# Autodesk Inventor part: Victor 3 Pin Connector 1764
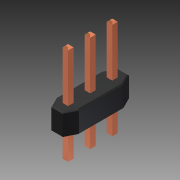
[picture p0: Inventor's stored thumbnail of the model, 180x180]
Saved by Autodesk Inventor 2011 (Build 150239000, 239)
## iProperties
Shininess: 64.0
Length Units: 11272
Angle Units: 11279
Time Units: 11290
Mass Units: 11286
Length Display Precision: 3
Angle Display Precision: 2
Compacted: True
Part Number: Victor 3 Pin Connector 1764
Document SubType Name: Modeling
Created: 2005-12
Designer: Owner
Material: ABS Plastic
Density: 1 g/cm^3
Density: 0.0
Volumn: 0.0
Area: 0.0
PropertySet Name: Model Information
Control State: 0
Master: False
Checked Out: False
Author: Owner
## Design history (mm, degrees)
sketch "Sketch1"
  geometry: L1 (0, 0)-(2.54, 0); L2 (2.54, 0)-(2.54, 7.62); L3 (2.54, 7.62)-(0, 7.62); L4 (0, 7.62)-(0, 0); L5 (0.953, 4.128)-(1.587, 4.128); L6 (1.587, 4.128)-(1.587, 3.493); L7 (1.587, 3.493)-(0.953, 3.493); L8 (0.953, 3.493)-(0.953, 4.128); L9 (0.953, 1.587)-(1.587, 1.587); L10 (1.587, 1.587)-(1.587, 0.953); L11 (1.587, 0.953)-(0.953, 0.953); L12 (0.953, 0.953)-(0.953, 1.587); L13 (0.953, 3.81)-(0, 3.81); L14 (1.587, 1.27)-(2.54, 1.27); L15 (0.953, 6.033)-(1.587, 6.033); L16 (1.587, 6.033)-(1.587, 6.667); L17 (1.587, 6.667)-(0.953, 6.667); L18 (0.953, 6.667)-(0.953, 6.033)
  constraints: 36 end point, 8 parallel, 6 equal length, 6 perpendicular, 4 horizontal, 3 midpoint, 2 collinear, 1 point on line, 1 other
  dimensions: "d3" = 2.54 distance of L1.start L1.end; "d4" = 7.62 distance of L3.end L1.start; "d5" = 0.635 distance of L5.end L6.end; "d6" = 2.54 distance between parallel lines of L11 L7; "d7" = 0.9525 distance between parallel lines of L1 L11; "d25" = 2.54 distance between parallel lines of L17 L5
extrude "Extrusion1" new body sketch "Sketch1" distance "d8" = 2.54; taper "d9" = 0 deg
chamfer "Chamfer1" distance "d10" = 1.27; stored, may be unused: second distance "d11" = 0.635, angle "d26" = 45 deg
chamfer "Chamfer2" distance "d12" = 1.27; stored, may be unused: second distance "d13" = 0.635, angle "d27" = 45 deg
chamfer "Chamfer3" distance "d14" = 1.27; stored, may be unused: second distance "d15" = 0.635, angle "d28" = 45 deg
chamfer "Chamfer4" distance "d16" = 1.27; stored, may be unused: second distance "d17" = 0.635, angle "d29" = 45 deg
workplane "Work Plane1"
sketch "Sketch2"
  geometry: L1 (-1.587, 4.128)-(-0.953, 4.128) reference; L2 (-1.587, 3.493)-(-1.587, 4.128) reference; L3 (-0.953, 4.128)-(-0.953, 3.493) reference; L4 (-0.953, 3.493)-(-1.587, 3.493) reference; L5 (-1.587, 1.587)-(-0.953, 1.587) reference; L6 (-0.953, 1.587)-(-0.953, 0.953) reference; L7 (-0.953, 0.953)-(-1.587, 0.953) reference; L8 (-1.587, 0.953)-(-1.587, 1.587) reference; L9 (-0.953, 6.667)-(-0.953, 6.033) reference; L10 (-0.953, 6.033)-(-1.587, 6.033) reference; L11 (-1.587, 6.033)-(-1.587, 6.667) reference; L12 (-1.587, 6.667)-(-0.953, 6.667) reference
extrude "Extrusion2" join sketch "Sketch2" distance "d19" = 11.43; taper "d20" = 0 deg
chamfer "Chamfer5" distance "d21" = 0.1778; stored, may be unused: second distance "d22" = 0.635, angle "d30" = 45 deg
chamfer "Chamfer6" distance "d23" = 0.127; stored, may be unused: second distance "d24" = 0.635, angle "d31" = 45 deg
body "Solid1"
other parameters: "d18" = 3.175
